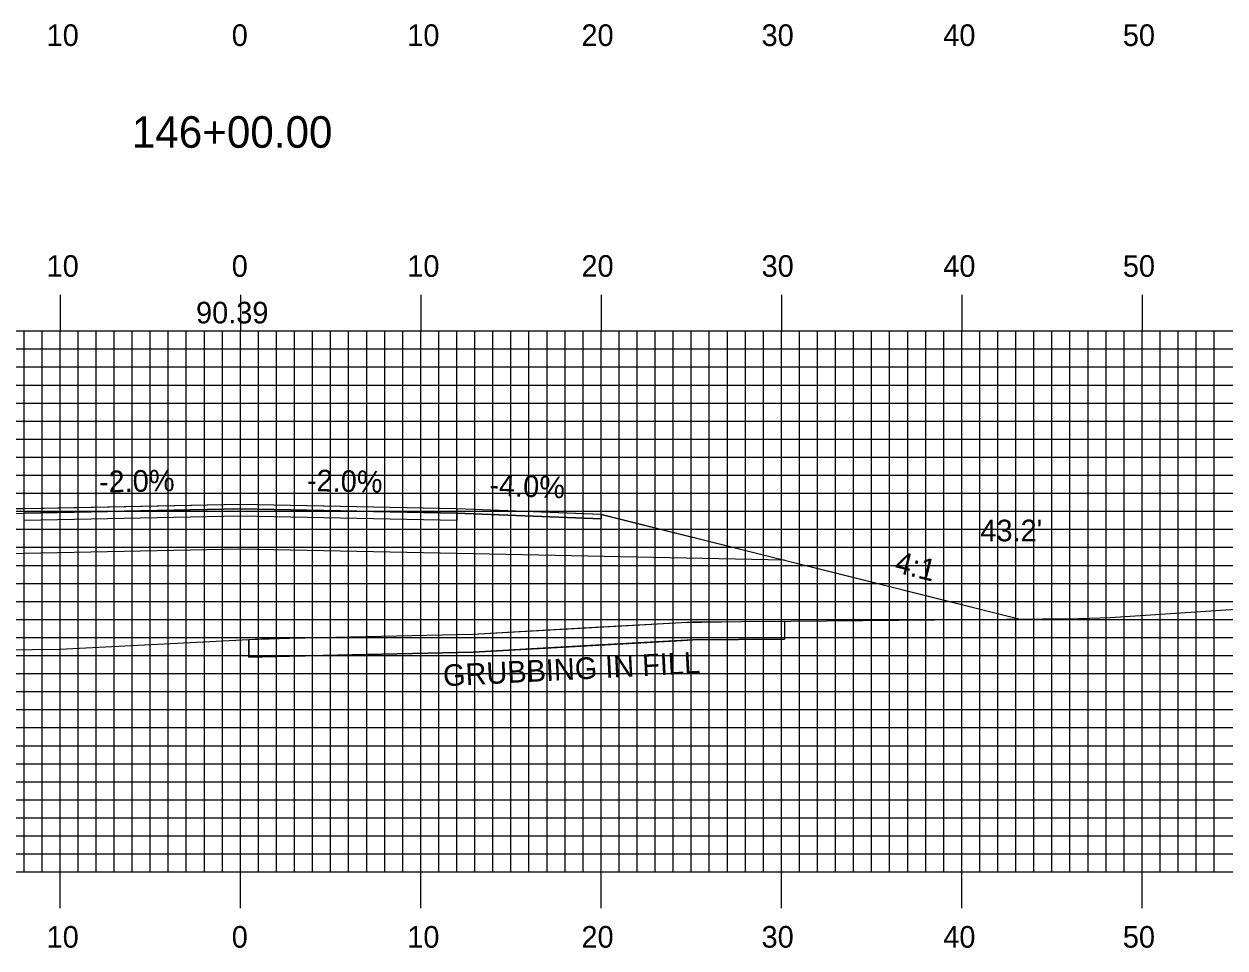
# Model space of a CAD drawing. Extents: x 1777531 to 1777875, y 442591 to 442811.
# Drawn here: x 1777685.3 to 1777751.9, y 442649.4 to 442700.7 of the extents above; entities that cross this region are included whole.
import ezdxf

# ---------------------------------------------------------------- set-up
doc = ezdxf.new("R2010")
doc.units = 0
for name, color, linetype in [('ANNOTATION', 7, 'Continuous'), ('D_Roadway_Centerline', 7, 'Continuous'), ('D_Roadway_Centerline_Text', 7, 'Continuous'), ('D_Roadway_Edge_Shoulder', 7, 'Continuous'), ('D_Roadway_Edge_TW', 7, 'Continuous'), ('D_Roadway_Pavement', 7, 'Continuous'), ('D_Roadway_SlopeLines', 7, 'Continuous'), ('D_Roadway_SubGrade', 7, 'Continuous'), ('D_Text_Standard', 7, 'Continuous'), ('GRUBBING IN FILL', 7, 'Continuous'), ('H_V ANNOTATION', 7, 'Continuous'), ('MAJOR', 7, 'Continuous'), ('MINOR', 7, 'Continuous'), ('S_Roadway_Centerline', 7, 'Continuous')]:
    doc.layers.add(name, color=color, linetype=linetype)

msp = doc.modelspace()

# ---------------------------------------------------------------- linework, layer by layer
at = {"layer": 'D_Roadway_Centerline'}
msp.add_lwpolyline([(1777648.264, 442664.825), (1777648.266, 442664.826), (1777654.447, 442666.886), (1777665.203, 442670.471), (1777665.277, 442670.496), (1777665.285, 442670.498), (1777666.523, 442670.808), (1777667.103, 442670.953), (1777677.277, 442673.496), (1777685.277, 442673.816), (1777686.395, 442673.839), (1777697.277, 442674.056), (1777709.262, 442673.816), (1777709.276, 442673.816), (1777717.263, 442673.497), (1777717.277, 442673.496), (1777717.294, 442673.492), (1777727.451, 442670.953), (1777730.135, 442670.282), (1777740.516, 442667.686)], dxfattribs=at)
at = {"layer": 'D_Roadway_Edge_Shoulder'}
for points in [[(1777685.277, 442673.816), (1777677.277, 442673.496), (1777677.277, 442673.246), (1777685.277, 442673.566)], [(1777709.276, 442673.816), (1777717.277, 442673.496), (1777717.277, 442673.246), (1777709.276, 442673.566)]]:
    msp.add_lwpolyline(points, close=True, dxfattribs=at)
at = {"layer": 'D_Roadway_Edge_TW'}
msp.add_lwpolyline([(1777685.277, 442673.566), (1777685.277, 442673.816), (1777697.277, 442674.056), (1777709.276, 442673.816), (1777709.276, 442673.566), (1777697.277, 442673.806)], close=True, dxfattribs=at)
at = {"layer": 'D_Roadway_Pavement'}
msp.add_lwpolyline([(1777685.277, 442673.15), (1777685.277, 442673.566), (1777697.277, 442673.806), (1777709.276, 442673.566), (1777709.276, 442673.15), (1777697.277, 442673.39)], close=True, dxfattribs=at)
at = {"layer": 'D_Roadway_SlopeLines'}
msp.add_lwpolyline([(1777717.277, 442673.496), (1777727.451, 442670.953), (1777740.516, 442667.686)], dxfattribs=at)
at = {"layer": 'D_Roadway_SubGrade'}
msp.add_lwpolyline([(1777685.277, 442671.316), (1777667.103, 442670.953), (1777677.277, 442673.496), (1777677.277, 442673.246), (1777685.277, 442673.566), (1777697.277, 442673.806), (1777709.276, 442673.566), (1777717.277, 442673.246), (1777717.277, 442673.496), (1777727.451, 442670.953), (1777709.276, 442671.316), (1777697.277, 442671.556)], close=True, dxfattribs=at)
at = {"layer": 'GRUBBING IN FILL'}
for p, q in [((1777727.451, 442667.566), (1777727.451, 442666.566)), ((1777727.451, 442667.566), (1777727.451, 442666.566)), ((1777697.742, 442666.547), (1777697.742, 442665.566)), ((1777697.742, 442666.547), (1777697.742, 442665.566))]:
    msp.add_line(p, q, dxfattribs=at)
msp.add_lwpolyline([(1777697.742, 442666.547), (1777699.998, 442666.62), (1777705.081, 442666.737), (1777710.165, 442666.853), (1777715.949, 442667.176), (1777721.734, 442667.499), (1777725.065, 442667.549), (1777727.451, 442667.566), (1777727.451, 442666.566), (1777724.91, 442666.548), (1777722.369, 442666.529), (1777715.995, 442666.177), (1777710.204, 442665.854), (1777705.113, 442665.737), (1777697.742, 442665.566)], close=True, dxfattribs=at)
msp.add_lwpolyline([(1777697.742, 442666.547), (1777699.998, 442666.62), (1777705.081, 442666.737), (1777710.165, 442666.853), (1777715.949, 442667.176), (1777721.734, 442667.499), (1777725.065, 442667.549), (1777727.451, 442667.566), (1777727.451, 442666.566), (1777724.91, 442666.548), (1777722.369, 442666.529), (1777715.995, 442666.177), (1777710.204, 442665.854), (1777705.113, 442665.737), (1777697.742, 442665.566)], close=True, dxfattribs=at)
msp.add_lwpolyline([(1777697.742, 442665.566), (1777700.021, 442665.621), (1777710.204, 442665.854), (1777721.786, 442666.5), (1777722.369, 442666.529), (1777727.451, 442666.567)], dxfattribs=at)
msp.add_lwpolyline([(1777697.742, 442665.566), (1777700.021, 442665.621), (1777710.204, 442665.854), (1777721.786, 442666.5), (1777722.369, 442666.529), (1777727.451, 442666.567)], dxfattribs=at)
at = {"layer": 'MAJOR'}
for p, q in [((1777687.277, 442685.669), (1777687.277, 442683.665)), ((1777697.277, 442685.669), (1777697.277, 442683.665)), ((1777707.277, 442685.669), (1777707.277, 442683.665)), ((1777717.277, 442685.669), (1777717.277, 442683.665)), ((1777727.277, 442685.669), (1777727.277, 442683.665)), ((1777737.277, 442685.669), (1777737.277, 442683.665)), ((1777747.277, 442685.669), (1777747.277, 442683.665)), ((1777557.277, 442683.665), (1777837.277, 442683.665)), ((1777557.277, 442683.665), (1777837.277, 442683.665)), ((1777687.277, 442653.665), (1777687.277, 442683.665)), ((1777697.277, 442653.665), (1777697.277, 442683.665)), ((1777707.277, 442653.665), (1777707.277, 442683.665)), ((1777717.277, 442653.665), (1777717.277, 442683.665)), ((1777727.277, 442653.665), (1777727.277, 442683.665)), ((1777737.277, 442653.665), (1777737.277, 442683.665)), ((1777747.277, 442653.665), (1777747.277, 442683.665)), ((1777557.277, 442678.665), (1777837.277, 442678.665)), ((1777557.277, 442673.665), (1777837.277, 442673.665)), ((1777557.277, 442668.665), (1777837.277, 442668.665)), ((1777557.277, 442663.665), (1777837.277, 442663.665)), ((1777557.277, 442658.665), (1777837.277, 442658.665)), ((1777557.277, 442653.665), (1777837.277, 442653.665)), ((1777557.277, 442653.665), (1777837.277, 442653.665)), ((1777687.277, 442651.661), (1777687.277, 442653.665)), ((1777697.277, 442651.661), (1777697.277, 442653.665)), ((1777707.277, 442651.661), (1777707.277, 442653.665)), ((1777717.277, 442651.661), (1777717.277, 442653.665)), ((1777727.277, 442651.661), (1777727.277, 442653.665)), ((1777737.277, 442651.661), (1777737.277, 442653.665)), ((1777747.277, 442651.661), (1777747.277, 442653.665))]:
    msp.add_line(p, q, dxfattribs=at)
at = {"layer": 'MINOR'}
for p, q in [((1777685.277, 442653.665), (1777685.277, 442683.665)), ((1777686.277, 442653.665), (1777686.277, 442683.665)), ((1777688.277, 442653.665), (1777688.277, 442683.665)), ((1777689.277, 442653.665), (1777689.277, 442683.665)), ((1777690.277, 442653.665), (1777690.277, 442683.665)), ((1777691.277, 442653.665), (1777691.277, 442683.665)), ((1777692.277, 442653.665), (1777692.277, 442683.665)), ((1777693.277, 442653.665), (1777693.277, 442683.665)), ((1777694.277, 442653.665), (1777694.277, 442683.665)), ((1777695.277, 442653.665), (1777695.277, 442683.665)), ((1777696.277, 442653.665), (1777696.277, 442683.665)), ((1777698.277, 442653.665), (1777698.277, 442683.665)), ((1777699.277, 442653.665), (1777699.277, 442683.665)), ((1777700.277, 442653.665), (1777700.277, 442683.665)), ((1777701.277, 442653.665), (1777701.277, 442683.665)), ((1777702.277, 442653.665), (1777702.277, 442683.665)), ((1777703.277, 442653.665), (1777703.277, 442683.665)), ((1777704.277, 442653.665), (1777704.277, 442683.665)), ((1777705.277, 442653.665), (1777705.277, 442683.665)), ((1777706.277, 442653.665), (1777706.277, 442683.665)), ((1777708.277, 442653.665), (1777708.277, 442683.665)), ((1777709.277, 442653.665), (1777709.277, 442683.665)), ((1777710.277, 442653.665), (1777710.277, 442683.665)), ((1777711.277, 442653.665), (1777711.277, 442683.665)), ((1777712.277, 442653.665), (1777712.277, 442683.665)), ((1777713.277, 442653.665), (1777713.277, 442683.665)), ((1777714.277, 442653.665), (1777714.277, 442683.665)), ((1777715.277, 442653.665), (1777715.277, 442683.665)), ((1777716.277, 442653.665), (1777716.277, 442683.665)), ((1777718.277, 442653.665), (1777718.277, 442683.665)), ((1777719.277, 442653.665), (1777719.277, 442683.665)), ((1777720.277, 442653.665), (1777720.277, 442683.665)), ((1777721.277, 442653.665), (1777721.277, 442683.665)), ((1777722.277, 442653.665), (1777722.277, 442683.665)), ((1777723.277, 442653.665), (1777723.277, 442683.665)), ((1777724.277, 442653.665), (1777724.277, 442683.665)), ((1777725.277, 442653.665), (1777725.277, 442683.665)), ((1777726.277, 442653.665), (1777726.277, 442683.665)), ((1777728.277, 442653.665), (1777728.277, 442683.665)), ((1777729.277, 442653.665), (1777729.277, 442683.665)), ((1777730.277, 442653.665), (1777730.277, 442683.665)), ((1777731.277, 442653.665), (1777731.277, 442683.665)), ((1777732.277, 442653.665), (1777732.277, 442683.665)), ((1777733.277, 442653.665), (1777733.277, 442683.665)), ((1777734.277, 442653.665), (1777734.277, 442683.665)), ((1777735.277, 442653.665), (1777735.277, 442683.665)), ((1777736.277, 442653.665), (1777736.277, 442683.665)), ((1777738.277, 442653.665), (1777738.277, 442683.665)), ((1777739.277, 442653.665), (1777739.277, 442683.665)), ((1777740.277, 442653.665), (1777740.277, 442683.665)), ((1777741.277, 442653.665), (1777741.277, 442683.665)), ((1777742.277, 442653.665), (1777742.277, 442683.665)), ((1777743.277, 442653.665), (1777743.277, 442683.665)), ((1777744.277, 442653.665), (1777744.277, 442683.665)), ((1777745.277, 442653.665), (1777745.277, 442683.665)), ((1777746.277, 442653.665), (1777746.277, 442683.665)), ((1777748.277, 442653.665), (1777748.277, 442683.665)), ((1777749.277, 442653.665), (1777749.277, 442683.665)), ((1777750.277, 442653.665), (1777750.277, 442683.665)), ((1777751.277, 442653.665), (1777751.277, 442683.665)), ((1777557.277, 442682.665), (1777837.277, 442682.665)), ((1777557.277, 442681.665), (1777837.277, 442681.665)), ((1777557.277, 442680.665), (1777837.277, 442680.665)), ((1777557.277, 442679.665), (1777837.277, 442679.665)), ((1777557.277, 442677.665), (1777837.277, 442677.665)), ((1777557.277, 442676.665), (1777837.277, 442676.665)), ((1777557.277, 442675.665), (1777837.277, 442675.665)), ((1777557.277, 442674.665), (1777837.277, 442674.665)), ((1777557.277, 442672.665), (1777837.277, 442672.665)), ((1777557.277, 442671.665), (1777837.277, 442671.665)), ((1777557.277, 442670.665), (1777837.277, 442670.665)), ((1777557.277, 442669.665), (1777837.277, 442669.665)), ((1777557.277, 442667.665), (1777837.277, 442667.665)), ((1777557.277, 442666.665), (1777837.277, 442666.665)), ((1777557.277, 442665.665), (1777837.277, 442665.665)), ((1777557.277, 442664.665), (1777837.277, 442664.665)), ((1777557.277, 442662.665), (1777837.277, 442662.665)), ((1777557.277, 442661.665), (1777837.277, 442661.665)), ((1777557.277, 442660.665), (1777837.277, 442660.665)), ((1777557.277, 442659.665), (1777837.277, 442659.665)), ((1777557.277, 442657.665), (1777837.277, 442657.665)), ((1777557.277, 442656.665), (1777837.277, 442656.665)), ((1777557.277, 442655.665), (1777837.277, 442655.665)), ((1777557.277, 442654.665), (1777837.277, 442654.665))]:
    msp.add_line(p, q, dxfattribs=at)
at = {"layer": 'S_Roadway_Centerline'}
msp.add_lwpolyline([(1777631.326, 442664.6), (1777640.64, 442664.628), (1777650.949, 442664.895), (1777654.292, 442665.032), (1777672.947, 442665.79), (1777674.835, 442665.867), (1777675.151, 442665.875), (1777687.255, 442666.018), (1777698.469, 442666.584), (1777699.998, 442666.62), (1777710.165, 442666.853), (1777721.734, 442667.499), (1777722.341, 442667.529), (1777727.789, 442667.57), (1777743.766, 442667.717), (1777745.497, 442667.775), (1777756.941, 442668.54)], dxfattribs=at)

# ---------------------------------------------------------------- texts
at = {"layer": 'ANNOTATION'}
for s, rotation, p in [('-2.0%', 1.14576, (1777689.442, 442674.7)), ('-2.0%', 358.85417, (1777700.955, 442674.783)), ('-4.0%', 357.70946, (1777711.061, 442674.546)), ('4:1', 345.96092, (1777733.49, 442670.305))]:
    msp.add_text(s, height=1.2, rotation=rotation, dxfattribs=at).set_placement(p)
at = {"layer": 'D_Roadway_Centerline'}
for s, p in [('C', (1777697.272, 442674.056)), ('L', (1777697.277, 442674.049))]:
    msp.add_text(s, height=0.0146, dxfattribs=at).set_placement(p)
at = {"layer": 'D_Roadway_Centerline_Text'}
msp.add_text('90.39', height=1.2, dxfattribs=at).set_placement((1777694.815, 442684.081))
at = {"layer": 'D_Text_Standard'}
msp.add_text("43.2'", height=1.2, dxfattribs=at).set_placement((1777738.305, 442671.998))
at = {"layer": 'GRUBBING IN FILL'}
msp.add_text('GRUBBING IN FILL', height=1.2, rotation=2.95705, dxfattribs=at).set_placement((1777708.543, 442663.954))
at = {"layer": 'H_V ANNOTATION'}
for s, height, p in [('10', 1.2, (1777686.528, 442699.465)), ('0', 1.2, (1777696.795, 442699.465)), ('10', 1.2, (1777706.528, 442699.465)), ('20', 1.2, (1777716.185, 442699.465)), ('30', 1.2, (1777726.174, 442699.465)), ('40', 1.2, (1777736.249, 442699.465)), ('50', 1.2, (1777746.206, 442699.465)), ('146+00.00', 1.75, (1777691.253, 442693.821)), ('10', 1.2, (1777686.528, 442686.665)), ('0', 1.2, (1777696.795, 442686.665)), ('10', 1.2, (1777706.528, 442686.665)), ('20', 1.2, (1777716.185, 442686.665)), ('30', 1.2, (1777726.174, 442686.665)), ('40', 1.2, (1777736.249, 442686.665)), ('50', 1.2, (1777746.206, 442686.665)), ('10', 1.2, (1777686.528, 442649.465)), ('0', 1.2, (1777696.795, 442649.465)), ('10', 1.2, (1777706.528, 442649.465)), ('20', 1.2, (1777716.185, 442649.465)), ('30', 1.2, (1777726.174, 442649.465)), ('40', 1.2, (1777736.249, 442649.465)), ('50', 1.2, (1777746.206, 442649.465))]:
    msp.add_text(s, height=height, dxfattribs=at).set_placement(p)

doc.saveas('drawing.dxf')
